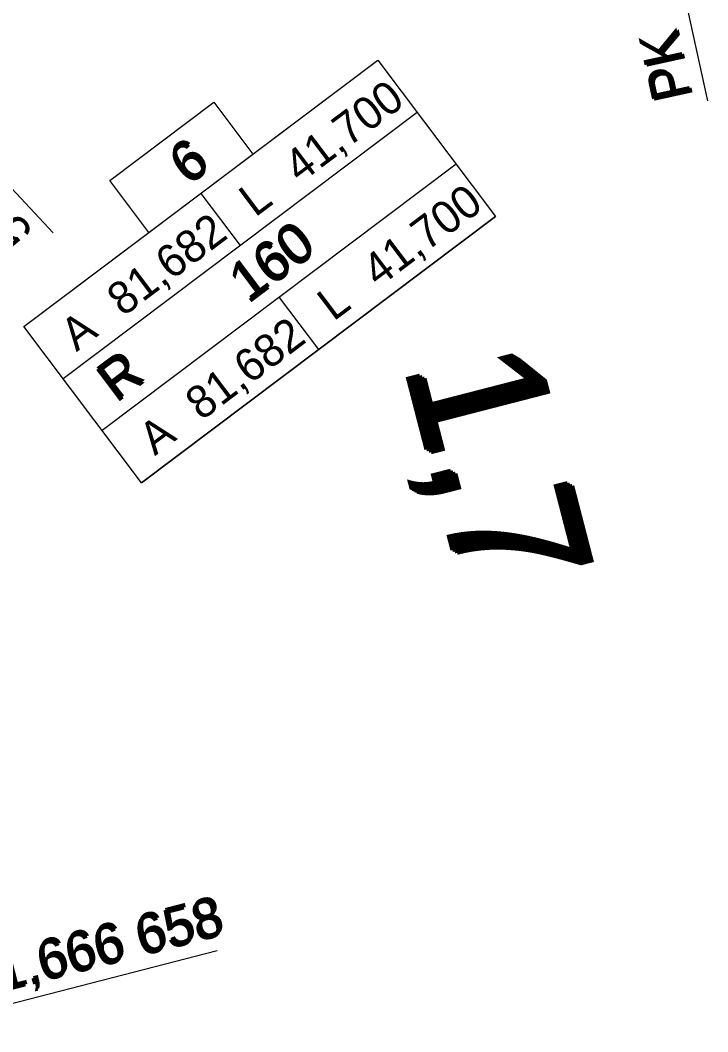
# Model space of a CAD drawing. Extents: x -606444 to -604546, y -1158114 to -1156869.
# Drawn here: x -606096 to -606043.2, y -1157451.6 to -1157373.9 of the extents above; entities that cross this region are included whole.
import ezdxf

# ---------------------------------------------------------------- set-up
doc = ezdxf.new("R2010")
doc.units = 0
for name, color, linetype in [('B_TRAM', 7, 'Continuous'), ('B_ZELEN', 7, 'Continuous'), ('NS_VB', 7, 'Continuous'), ('NS_VB_OBJ', 7, 'Continuous'), ('OSA', 7, 'Continuous'), ('OSAPOP', 7, 'Continuous')]:
    doc.layers.add(name, color=color, linetype=linetype)

msp = doc.modelspace()

# ---------------------------------------------------------------- linework, layer by layer
at = {"layer": 'B_TRAM'}
for centre, radius, start, end in [((-606024.976, -1157463.174), 165.563, 102.39239, 154.3928), ((-606025.003, -1157463.116), 154.5, 102.38755, 145.53878)]:
    msp.add_arc(centre, radius, start, end, dxfattribs=at)
at = {"layer": 'B_ZELEN'}
for radius, start, end in [(165.5, 102.38739, 151.55048), (154.5, 102.38746, 145.53878)]:
    msp.add_arc((-606025.003, -1157463.116), radius, start, end, dxfattribs=at)
at = {"layer": 'NS_VB'}
for radius, start, end in [(165.5, 102.38739, 151.55048), (154.5, 102.38746, 145.53878)]:
    msp.add_arc((-606025.003, -1157463.116), radius, start, end, dxfattribs=at)
at = {"layer": 'NS_VB_OBJ'}
for radius, end in [(165, 151.55041), (155, 145.53878)]:
    msp.add_arc((-606025.003, -1157463.116), radius, 108.14197, end, dxfattribs=at)
at = {"layer": 'OSA'}
for radius, start, end in [(162, 102.38741, 151.55), (160, 102.38743, 151.54972)]:
    msp.add_arc((-606025.003, -1157463.116), radius, start, end, dxfattribs=at)
at = {"layer": 'OSAPOP'}
for p, q in [((-606043.238, -1157380.095), (-606048.601, -1157355.677)), ((-606078.139, -1157384.207), (-606068.552, -1157376.991)), ((-606092.71, -1157401.432), (-606065.545, -1157380.986)), ((-606093.471, -1157390.231), (-606100.318, -1157382.943)), ((-606086.129, -1157390.221), (-606078.139, -1157384.207)), ((-606062.538, -1157384.981), (-606089.703, -1157405.427)), ((-606082.134, -1157387.214), (-606079.127, -1157391.209)), ((-606086.696, -1157409.422), (-606059.531, -1157388.975)), ((-606095.717, -1157397.438), (-606086.129, -1157390.221)), ((-606076.12, -1157395.204), (-606073.114, -1157399.199)), ((-606105.086, -1157451.579), (-606080.88, -1157445.328))]:
    msp.add_line(p, q, dxfattribs=at)
msp.add_lwpolyline([(-606095.717, -1157397.438), (-606068.552, -1157376.991), (-606059.531, -1157388.975), (-606086.696, -1157409.422)], close=True, dxfattribs=at)
msp.add_lwpolyline([(-606086.129, -1157390.221), (-606089.136, -1157386.226), (-606081.146, -1157380.213), (-606078.139, -1157384.207)], dxfattribs=at)

# ---------------------------------------------------------------- texts
for s, height, rotation, p in [('PK  1,363 927', 3, 102.38743, (-606044.511, -1157379.658)), ('PK  1,363 927', 3, 102.38743, (-606044.332, -1157379.772)), ('41,700', 2.5, 36.96857, (-606074.529, -1157386.496)), ('6', 3, 36.96857, (-606083.095, -1157386.686)), ('6', 3, 36.96857, (-606083.066, -1157386.476)), ('50,00', 2.8, 133.21014, (-606094.891, -1157390.083)), ('L', 2.5, 36.96857, (-606077.971, -1157389.087)), ('41,700', 2.5, 36.96857, (-606068.515, -1157394.486)), ('81,682', 2.5, 36.96857, (-606088.111, -1157396.719)), ('160', 3, 36.96857, (-606078.476, -1157395.538)), ('160', 3, 36.96857, (-606078.506, -1157395.748)), ('L', 2.5, 36.96857, (-606071.957, -1157397.077)), ('A', 2.5, 36.96857, (-606091.687, -1157399.411)), ('81,682', 2.5, 36.96857, (-606082.097, -1157404.709)), ('R', 3, 36.96857, (-606088.626, -1157403.365)), ('R', 3, 36.96857, (-606088.597, -1157403.156)), ('1,7', 10, 284.47993, (-606066.678, -1157400.34)), ('1,7', 10, 284.47993, (-606066.495, -1157400.448)), ('1,7', 10, 284.47993, (-606066.312, -1157400.555)), ('1,7', 10, 284.47993, (-606066.13, -1157400.663)), ('A', 2.5, 36.96857, (-606085.673, -1157407.4)), ('KT  1,666 658', 3, 14.47993, (-606104.658, -1157450.436)), ('KT  1,666 658', 3, 14.47993, (-606104.55, -1157450.253))]:
    msp.add_text(s, height=height, rotation=rotation, dxfattribs=at).set_placement(p)

doc.saveas('drawing.dxf')
